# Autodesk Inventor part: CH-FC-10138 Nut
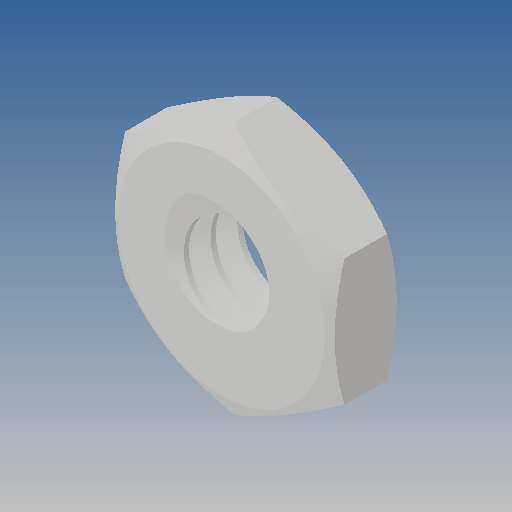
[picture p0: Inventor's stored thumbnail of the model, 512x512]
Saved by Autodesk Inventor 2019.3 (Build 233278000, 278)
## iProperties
Created: 2012-09
Part Number: CH-FC-10138 Nut
Material: Ogólny
Document SubType Name: Modeling
Designer: CADENGINEERING4
Density: 1 g/cm^3
Appearance: Domyślna
Author: CADENGINEERING4
Revision Number: ÈÎºÎ
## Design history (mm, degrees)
feature "ÇÐ³ý-É¨Ãè1"
node "Bryła1"
